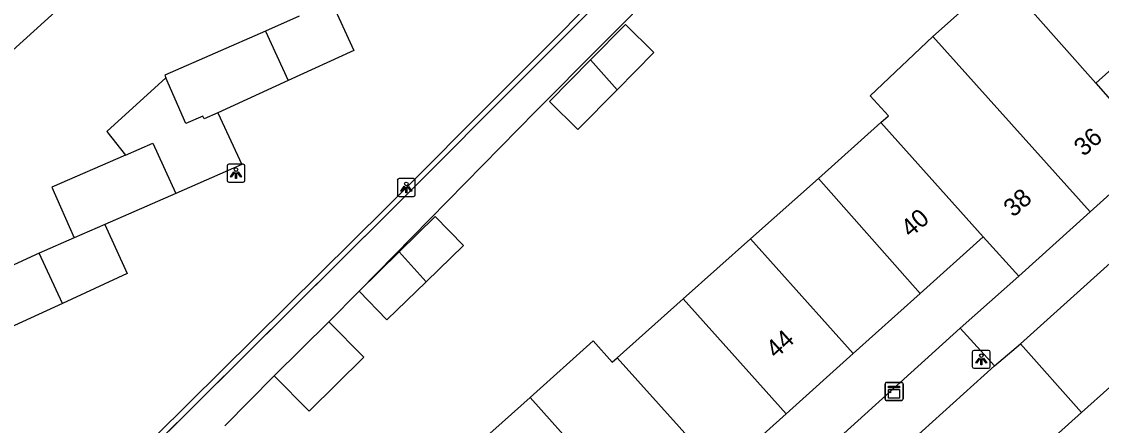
# Model space of a CAD drawing. Extents: x 162172 to 163187, y 382874 to 383684.
# Drawn here: x 162715.5 to 162775.8, y 383513 to 383535.5 of the extents above; entities that cross this region are included whole.
import ezdxf

# ---------------------------------------------------------------- set-up
doc = ezdxf.new("R2010")
doc.units = 0
for name, color, linetype in [('IMGEO_Hek', 7, 'Continuous'), ('IMGEO_Kast', 7, 'Continuous'), ('IMGEO_Lichtpunt', 7, 'Continuous'), ('IMGEO_Pand', 7, 'Continuous'), ('IMGEO_Pand_nummerreeks', 7, 'Continuous'), ('IMGEO_Rijbaan_lokaal_open', 7, 'Continuous'), ('IMGEO_Voetpad_open', 7, 'Continuous')]:
    doc.layers.add(name, color=color, linetype=linetype)

msp = doc.modelspace()

# ---------------------------------------------------------------- linework, layer by layer
at = {"layer": 'IMGEO_Hek'}
msp.add_lwpolyline([(162787.472, 383580.054), (162770.189, 383559.114), (162736.009, 383524.817), (162699.363, 383488.421)], dxfattribs=at)
at = {"layer": 'IMGEO_Kast'}
for p, q in [((162763.728, 383514.423), (162763.728, 383515.264)), ((162763.728, 383515.264), (162763.728, 383514.423)), ((162763.803, 383515.348), (162764.644, 383515.348)), ((162764.644, 383515.348), (162763.803, 383515.348)), ((162764.728, 383515.273), (162764.728, 383514.432)), ((162764.728, 383514.432), (162764.728, 383515.273)), ((162764.653, 383514.348), (162763.812, 383514.348)), ((162763.812, 383514.348), (162764.653, 383514.348))]:
    msp.add_line(p, q, dxfattribs=at)
for points in [[(162763.923, 383515.138), (162764.523, 383515.138), (162764.523, 383515.053), (162763.923, 383515.053), (162763.923, 383515.138)], [(162763.923, 383514.963), (162764.523, 383514.963), (162764.523, 383514.474), (162763.923, 383514.474), (162763.923, 383514.963)]]:
    msp.add_lwpolyline(points, dxfattribs=at)
msp.add_circle((162764.007, 383514.812), 0.0377, dxfattribs=at)
for centre, start, end in [((162763.806, 383515.27), 92.4484, 184.28452), ((162763.806, 383515.27), 92.4484, 184.28452), ((162764.65, 383515.27), 2.4484, 94.28452), ((162764.65, 383515.27), 2.4484, 94.28452), ((162763.806, 383514.426), 182.4484, 274.28452), ((162763.806, 383514.426), 182.4484, 274.28452), ((162764.65, 383514.426), 272.4484, 4.28452), ((162764.65, 383514.426), 272.4484, 4.28452)]:
    msp.add_arc(centre, 0.0779, start, end, dxfattribs=at)
at = {"layer": 'IMGEO_Lichtpunt'}
for p, q in [((162727.901, 383527.537), (162727.093, 383527.537)), ((162727.901, 383527.537), (162727.093, 383527.537)), ((162726.999, 383527.442), (162726.999, 383526.635)), ((162726.999, 383527.442), (162726.999, 383526.635)), ((162727.995, 383526.635), (162727.995, 383527.442)), ((162727.995, 383526.635), (162727.995, 383527.442)), ((162727.093, 383526.541), (162727.901, 383526.541)), ((162727.093, 383526.541), (162727.901, 383526.541)), ((162736.503, 383526.641), (162736.503, 383525.834)), ((162736.503, 383526.641), (162736.503, 383525.834)), ((162737.405, 383526.736), (162736.597, 383526.736)), ((162737.405, 383526.736), (162736.597, 383526.736)), ((162737.499, 383525.834), (162737.499, 383526.641)), ((162737.499, 383525.834), (162737.499, 383526.641)), ((162736.597, 383525.74), (162737.405, 383525.74)), ((162736.597, 383525.74), (162737.405, 383525.74)), ((162768.593, 383517.05), (162768.593, 383516.243)), ((162768.593, 383517.05), (162768.593, 383516.243)), ((162769.495, 383517.145), (162768.687, 383517.145)), ((162769.495, 383517.145), (162768.687, 383517.145)), ((162769.589, 383516.243), (162769.589, 383517.05)), ((162769.589, 383516.243), (162769.589, 383517.05)), ((162768.687, 383516.149), (162769.495, 383516.149)), ((162768.687, 383516.149), (162769.495, 383516.149))]:
    msp.add_line(p, q, dxfattribs=at)
for points in [[(162727.373, 383527.106), (162727.412, 383527.078), (162727.224, 383526.816), (162727.186, 383526.843), (162727.373, 383527.106)], [(162727.475, 383527.058), (162727.522, 383527.058), (162727.522, 383526.736), (162727.475, 383526.736), (162727.475, 383527.058)], [(162727.585, 383527.078), (162727.623, 383527.105), (162727.81, 383526.843), (162727.771, 383526.815), (162727.585, 383527.078)], [(162736.877, 383526.305), (162736.916, 383526.277), (162736.728, 383526.015), (162736.69, 383526.042), (162736.877, 383526.305)], [(162737.089, 383526.277), (162737.127, 383526.304), (162737.314, 383526.042), (162737.275, 383526.014), (162737.089, 383526.277)], [(162736.979, 383526.257), (162737.026, 383526.257), (162737.026, 383525.935), (162736.979, 383525.935), (162736.979, 383526.257)], [(162768.967, 383516.714), (162769.006, 383516.686), (162768.818, 383516.424), (162768.78, 383516.451), (162768.967, 383516.714)], [(162769.069, 383516.666), (162769.116, 383516.666), (162769.116, 383516.344), (162769.069, 383516.344), (162769.069, 383516.666)], [(162769.179, 383516.686), (162769.217, 383516.713), (162769.404, 383516.451), (162769.365, 383516.423), (162769.179, 383516.686)]]:
    msp.add_lwpolyline(points, dxfattribs=at)
for centre in [(162727.498, 383527.24), (162737.002, 383526.439), (162769.092, 383516.848)]:
    msp.add_circle(centre, 0.0994, dxfattribs=at)
for centre, start, end in [((162727.093, 383527.442), 90, 180), ((162727.093, 383527.442), 90, 180), ((162727.901, 383527.442), 0, 90), ((162727.901, 383527.442), 0, 90), ((162727.093, 383526.635), 180, 270), ((162727.093, 383526.635), 180, 270), ((162727.901, 383526.635), 270, 0), ((162727.901, 383526.635), 270, 360), ((162736.597, 383526.641), 90, 180), ((162736.597, 383526.641), 90, 180), ((162737.405, 383526.641), 0, 90), ((162737.405, 383526.641), 0, 90), ((162736.597, 383525.834), 180, 270), ((162736.597, 383525.834), 180, 270), ((162737.405, 383525.834), 270, 0), ((162737.405, 383525.834), 270, 360), ((162768.687, 383517.05), 90, 180), ((162768.687, 383517.05), 90, 180), ((162769.495, 383517.05), 0, 90), ((162769.495, 383517.05), 0, 90), ((162768.687, 383516.243), 180, 270), ((162768.687, 383516.243), 180, 270), ((162769.495, 383516.243), 270, 0), ((162769.495, 383516.243), 270, 360)]:
    msp.add_arc(centre, 0.0946, start, end, dxfattribs=at)
at = {"layer": 'IMGEO_Pand'}
for points in [[(162668.172, 383494.324), (162674.468, 383500), (162707.707, 383529.967), (162709.05, 383528.485), (162742.01, 383558.381), (162740.673, 383559.855), (162769.856, 383586.324), (162773.559, 383589.683)], [(162766.398, 383534.673), (162770.193, 383538.057)], [(162770.193, 383538.057), (162775.48, 383532.059)], [(162732.836, 383536.614), (162734.081, 383533.898), (162730.409, 383532.215)], [(162779.859, 383535.987), (162775.48, 383532.059)], [(162731.033, 383535.8), (162729.144, 383534.975)], [(162747.283, 383533.372), (162749.231, 383535.347), (162750.826, 383533.775), (162748.779, 383531.7)], [(162729.144, 383534.975), (162723.522, 383532.516), (162723.585, 383532.371)], [(162729.144, 383534.975), (162730.409, 383532.215)], [(162763.485, 383529.862), (162763.912, 383530.243), (162762.883, 383531.367), (162766.398, 383534.673)], [(162775.168, 383524.878), (162766.398, 383534.673)], [(162748.779, 383531.7), (162746.583, 383529.473), (162744.989, 383531.047), (162747.283, 383533.372)], [(162748.779, 383531.7), (162747.283, 383533.372)], [(162723.585, 383532.371), (162720.293, 383529.359), (162721.336, 383528.049)], [(162726.486, 383530.417), (162725.725, 383530.069), (162725.654, 383530.231), (162724.703, 383529.815), (162723.585, 383532.371)], [(162730.409, 383532.215), (162726.486, 383530.417)], [(162775.48, 383532.059), (162778.876, 383528.213), (162775.168, 383524.878)], [(162726.486, 383530.417), (162727.816, 383527.516), (162724.146, 383525.911)], [(162760, 383526.742), (162763.485, 383529.862)], [(162769.193, 383523.485), (162763.485, 383529.862)], [(162721.336, 383528.049), (162722.861, 383528.716), (162724.146, 383525.911)], [(162721.336, 383528.049), (162717.229, 383526.253), (162718.466, 383523.427)], [(162756.22, 383523.379), (162760, 383526.742)], [(162760, 383526.742), (162765.68, 383520.328)], [(162724.146, 383525.911), (162720.175, 383524.174)], [(162736.609, 383522.646), (162738.616, 383524.623), (162740.19, 383523.004), (162738.104, 383520.975)], [(162775.168, 383524.878), (162771.184, 383521.295)], [(162720.175, 383524.174), (162721.433, 383521.428), (162717.81, 383519.767)], [(162720.175, 383524.174), (162718.466, 383523.427)], [(162718.466, 383523.427), (162716.522, 383522.576)], [(162752.457, 383520.021), (162756.22, 383523.379)], [(162761.948, 383516.973), (162756.22, 383523.379)], [(162765.68, 383520.328), (162769.193, 383523.485)], [(162769.193, 383523.485), (162771.184, 383521.295)], [(162734.371, 383520.443), (162736.609, 383522.646)], [(162738.104, 383520.975), (162736.609, 383522.646)], [(162716.522, 383522.576), (162711.731, 383520.372), (162712.966, 383517.545)], [(162717.81, 383519.767), (162716.522, 383522.576)], [(162738.104, 383520.975), (162735.92, 383518.851), (162734.371, 383520.443)], [(162761.948, 383516.973), (162765.68, 383520.328)], [(162717.81, 383519.767), (162713.774, 383517.916)], [(162748.772, 383516.728), (162752.457, 383520.021)], [(162752.457, 383520.021), (162758.201, 383513.605)], [(162732.689, 383518.737), (162734.633, 383516.763), (162731.577, 383513.753), (162729.633, 383515.727)], [(162729.633, 383515.727), (162732.689, 383518.737)], [(162743.907, 383514.517), (162747.43, 383517.675), (162748.5, 383516.485), (162748.772, 383516.728)], [(162754.538, 383510.313), (162748.772, 383516.728)], [(162758.201, 383513.605), (162761.948, 383516.973)], [(162740.108, 383511.111), (162743.907, 383514.517)], [(162743.907, 383514.517), (162752.682, 383504.676)], [(162754.538, 383510.313), (162758.201, 383513.605)]]:
    msp.add_lwpolyline(points, dxfattribs=at)
at = {"layer": 'IMGEO_Rijbaan_lokaal_open'}
for points in [[(162688.137, 383479.847), (162689.577, 383481.14), (162691.809, 383481.476), (162735.856, 383525.085), (162769.966, 383559.316), (162787.269, 383580.28)], [(162771.287, 383517.512), (162780.938, 383526.198), (162780.973, 383526.23)], [(162769.831, 383516.272), (162771.287, 383517.512)], [(162771.287, 383517.512), (162774.683, 383513.676)], [(162769.831, 383516.272), (162761.751, 383508.982)], [(162774.683, 383513.676), (162777.843, 383516.5)], [(162763.769, 383503.865), (162774.683, 383513.676)]]:
    msp.add_lwpolyline(points, dxfattribs=at)
at = {"layer": 'IMGEO_Voetpad_open'}
for points in [[(162700.494, 383489.544), (162736.009, 383524.817), (162770.189, 383559.114), (162787.472, 383580.054)], [(162759.834, 383545.997), (162755.032, 383541.389), (162744.224, 383530.511), (162734.371, 383520.443)], [(162771.184, 383521.295), (162767.922, 383518.376)], [(162734.371, 383520.443), (162732.689, 383518.737)], [(162767.922, 383518.376), (162759.841, 383511.063)], [(162767.922, 383518.376), (162769.831, 383516.272)], [(162729.633, 383515.727), (162726.871, 383512.92)]]:
    msp.add_lwpolyline(points, dxfattribs=at)

# ---------------------------------------------------------------- texts
at = {"layer": 'IMGEO_Pand_nummerreeks'}
for s, rotation, p in [('36', 41.51068, (162774.81, 383527.934)), ('38', 41.55261, (162770.88, 383524.537)), ('40', 40.94065, (162765.144, 383523.407)), ('44', 42.13759, (162757.63, 383516.65))]:
    msp.add_text(s, height=1, rotation=rotation, dxfattribs=at).set_placement(p)

doc.saveas('drawing.dxf')
